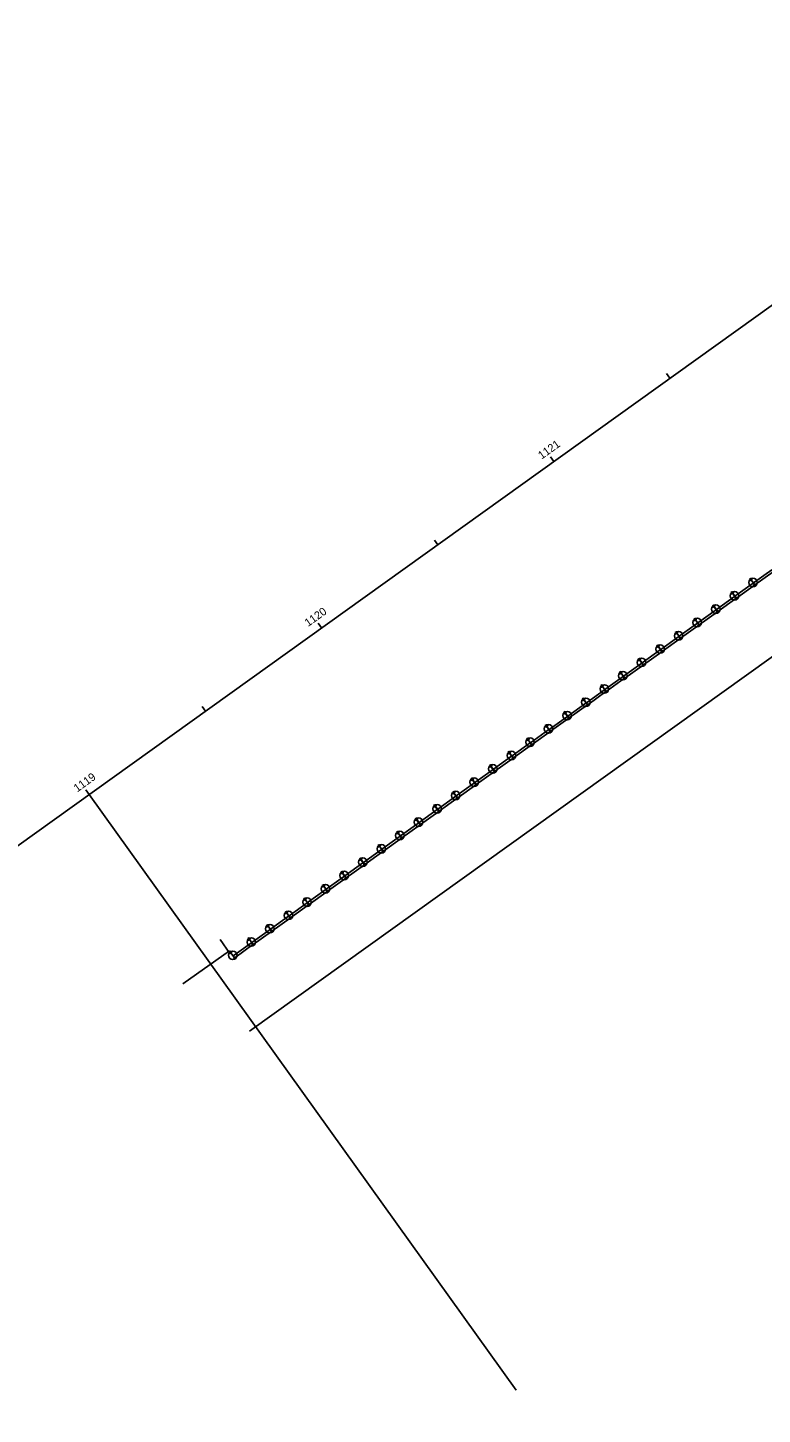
# Model space of a CAD drawing. Extents: x 2079879 to 2092887, y 778083 to 784051.
# Drawn here: x 2083884.9 to 2084142, y 780721.7 to 781206.9 of the extents above; entities that cross this region are included whole.
import ezdxf

# ---------------------------------------------------------------- set-up
doc = ezdxf.new("R2010")
doc.units = 0
for name, color, linetype in [('SC_Scratch1', 7, 'Continuous'), ('SH_Data', 7, 'Continuous'), ('SH_Text', 7, 'Continuous'), ('XS_X_Pavt', 7, 'Continuous')]:
    doc.layers.add(name, color=color, linetype=linetype)

msp = doc.modelspace()

# ---------------------------------------------------------------- linework, layer by layer
at = {"layer": 'SC_Scratch1'}
for p, q in [((2079923.52, 778084.44), (2085691.45, 782217.74)), ((2084109.66, 781084.22), (2084108.49, 781085.85)), ((2084069.02, 781055.1), (2084067.85, 781056.73)), ((2084028.37, 781025.98), (2084027.21, 781027.6)), ((2083987.73, 780996.85), (2083986.57, 780998.48)), ((2083947.09, 780967.73), (2083945.93, 780969.35)), ((2083906.45, 780938.6), (2083905.28, 780940.23))]:
    msp.add_line(p, q, dxfattribs=at)
at = {"layer": 'SH_Data'}
for p, q in [((2083962.54, 780855.77), (2084452.4, 781206.81)), ((2084138.06, 781013.69), (2084137.63, 781014.3)), ((2084131.56, 781009.03), (2084131.13, 781009.64)), ((2084125.06, 781004.37), (2084124.62, 781004.98)), ((2084118.55, 780999.71), (2084118.12, 781000.32)), ((2084112.05, 780995.05), (2084111.62, 780995.66)), ((2084105.55, 780990.39), (2084105.11, 780991)), ((2084099.04, 780985.73), (2084098.61, 780986.34)), ((2084092.54, 780981.07), (2084092.11, 780981.68)), ((2084086.04, 780976.41), (2084085.61, 780977.02)), ((2084079.54, 780971.75), (2084079.1, 780972.36)), ((2084073.03, 780967.09), (2084072.6, 780967.7)), ((2084066.53, 780962.43), (2084066.1, 780963.04)), ((2084060.03, 780957.77), (2084059.6, 780958.38)), ((2084053.53, 780953.11), (2084053.09, 780953.72)), ((2084040.52, 780943.79), (2084040.09, 780944.4)), ((2084047.02, 780948.45), (2084046.59, 780949.06)), ((2083906.45, 780938.6), (2084055.81, 780730.17)), ((2084027.51, 780934.47), (2084027.08, 780935.08)), ((2084021.01, 780929.81), (2084020.58, 780930.42)), ((2084014.51, 780925.15), (2084014.08, 780925.76)), ((2084008.01, 780920.49), (2084007.57, 780921.1)), ((2084001.5, 780915.83), (2084001.07, 780916.44)), ((2083995, 780911.17), (2083994.57, 780911.78)), ((2083988.5, 780906.51), (2083988.07, 780907.12)), ((2083982, 780901.85), (2083981.56, 780902.46)), ((2083975.49, 780897.19), (2083975.06, 780897.8)), ((2083968.99, 780892.53), (2083968.56, 780893.14)), ((2083955.65, 780882.97), (2083952.19, 780887.87)), ((2083962.49, 780887.87), (2083962.05, 780888.48)), ((2083955.55, 780883.82), (2083939.21, 780872.29)), ((2083955.98, 780883.21), (2083955.55, 780883.82))]:
    msp.add_line(p, q, dxfattribs=at)
at = {"layer": 'SH_Text'}
for centre in [(2084138.71, 781012.78), (2084132.21, 781008.12), (2084125.71, 781003.46), (2084119.21, 780998.8), (2084112.7, 780994.14), (2084106.2, 780989.48), (2084099.7, 780984.82), (2084093.19, 780980.16), (2084086.69, 780975.5), (2084080.19, 780970.84), (2084073.69, 780966.18), (2084067.18, 780961.52), (2084060.68, 780956.86), (2084054.18, 780952.2), (2084041.17, 780942.88), (2084047.68, 780947.54), (2084034.67, 780938.22), (2084028.17, 780933.56), (2084021.66, 780928.9), (2084015.16, 780924.24), (2084008.66, 780919.58), (2084002.16, 780914.92), (2083995.65, 780910.26), (2083989.15, 780905.6), (2083982.65, 780900.94), (2083976.15, 780896.28), (2083969.64, 780891.62), (2083963.14, 780886.96), (2083956.64, 780882.3)]:
    msp.add_circle(centre, 1.5, dxfattribs=at)
at = {"layer": 'XS_X_Pavt'}
for points in [[(2084138.93, 781012.62), (2084145.29, 781017.19), (2084145.78, 781016.51), (2084139.41, 781011.95)], [(2084132.42, 781007.96), (2084138.79, 781012.53), (2084139.28, 781011.85), (2084132.91, 781007.29)], [(2084137.72, 781013.44), (2084138.4, 781013.93), (2084138.42, 781013.9), (2084138.11, 781013.67), (2084139.37, 781011.92), (2084139.68, 781012.14), (2084139.71, 781012.11), (2084139.03, 781011.62), (2084139, 781011.66), (2084139.32, 781011.88), (2084138.06, 781013.64), (2084137.75, 781013.41)], [(2084125.92, 781003.3), (2084132.29, 781007.87), (2084132.77, 781007.19), (2084126.41, 781002.63)], [(2084131.22, 781008.78), (2084131.9, 781009.27), (2084131.92, 781009.24), (2084131.61, 781009.01), (2084132.87, 781007.26), (2084133.18, 781007.48), (2084133.2, 781007.45), (2084132.53, 781006.96), (2084132.5, 781007), (2084132.82, 781007.22), (2084131.56, 781008.98), (2084131.24, 781008.75)], [(2084119.42, 780998.64), (2084125.78, 781003.21), (2084126.27, 781002.53), (2084119.9, 780997.97)], [(2084124.72, 781004.12), (2084125.39, 781004.61), (2084125.42, 781004.58), (2084125.1, 781004.35), (2084126.36, 781002.6), (2084126.68, 781002.82), (2084126.7, 781002.79), (2084126.02, 781002.3), (2084126, 781002.34), (2084126.31, 781002.56), (2084125.05, 781004.32), (2084124.74, 781004.09)], [(2084112.91, 780993.98), (2084119.28, 780998.55), (2084119.77, 780997.87), (2084113.4, 780993.31)], [(2084118.21, 780999.46), (2084118.89, 780999.95), (2084118.92, 780999.92), (2084118.6, 780999.69), (2084119.86, 780997.94), (2084120.17, 780998.16), (2084120.2, 780998.13), (2084119.52, 780997.64), (2084119.5, 780997.68), (2084119.81, 780997.9), (2084118.55, 780999.66), (2084118.24, 780999.43)], [(2084106.41, 780989.32), (2084112.78, 780993.89), (2084113.26, 780993.21), (2084106.9, 780988.65)], [(2084111.71, 780994.8), (2084112.39, 780995.29), (2084112.41, 780995.26), (2084112.1, 780995.03), (2084113.36, 780993.28), (2084113.67, 780993.5), (2084113.69, 780993.47), (2084113.02, 780992.98), (2084112.99, 780993.02), (2084113.31, 780993.24), (2084112.05, 780995), (2084111.74, 780994.77)], [(2084099.91, 780984.66), (2084106.28, 780989.23), (2084106.76, 780988.55), (2084100.39, 780983.99)], [(2084105.21, 780990.14), (2084105.89, 780990.63), (2084105.91, 780990.6), (2084105.6, 780990.37), (2084106.85, 780988.62), (2084107.17, 780988.84), (2084107.19, 780988.81), (2084106.51, 780988.32), (2084106.49, 780988.36), (2084106.8, 780988.58), (2084105.55, 780990.34), (2084105.23, 780990.11)], [(2084093.41, 780980), (2084099.77, 780984.57), (2084100.26, 780983.89), (2084093.89, 780979.33)], [(2084098.71, 780985.48), (2084099.38, 780985.97), (2084099.41, 780985.94), (2084099.09, 780985.71), (2084100.35, 780983.96), (2084100.67, 780984.18), (2084100.69, 780984.15), (2084100.01, 780983.66), (2084099.99, 780983.7), (2084100.3, 780983.92), (2084099.04, 780985.68), (2084098.73, 780985.45)], [(2084086.9, 780975.34), (2084093.27, 780979.91), (2084093.76, 780979.23), (2084087.39, 780974.67)], [(2084092.2, 780980.83), (2084092.88, 780981.31), (2084092.9, 780981.28), (2084092.59, 780981.05), (2084093.85, 780979.3), (2084094.16, 780979.52), (2084094.19, 780979.49), (2084093.51, 780979), (2084093.49, 780979.04), (2084093.8, 780979.26), (2084092.54, 780981.02), (2084092.23, 780980.79)], [(2084080.4, 780970.68), (2084086.77, 780975.25), (2084087.25, 780974.57), (2084080.89, 780970.01)], [(2084085.7, 780976.17), (2084086.38, 780976.65), (2084086.4, 780976.62), (2084086.09, 780976.39), (2084087.35, 780974.64), (2084087.66, 780974.86), (2084087.68, 780974.83), (2084087.01, 780974.34), (2084086.98, 780974.38), (2084087.3, 780974.6), (2084086.04, 780976.36), (2084085.72, 780976.13)], [(2084073.9, 780966.03), (2084080.27, 780970.59), (2084080.75, 780969.91), (2084074.38, 780965.35)], [(2084079.2, 780971.51), (2084079.88, 780971.99), (2084079.9, 780971.96), (2084079.59, 780971.73), (2084080.84, 780969.98), (2084081.16, 780970.2), (2084081.18, 780970.17), (2084080.5, 780969.68), (2084080.48, 780969.72), (2084080.79, 780969.94), (2084079.53, 780971.7), (2084079.22, 780971.47)], [(2084067.4, 780961.37), (2084073.76, 780965.93), (2084074.25, 780965.25), (2084067.88, 780960.69)], [(2084072.69, 780966.85), (2084073.37, 780967.33), (2084073.4, 780967.3), (2084073.08, 780967.07), (2084074.34, 780965.32), (2084074.65, 780965.54), (2084074.68, 780965.51), (2084074, 780965.02), (2084073.98, 780965.06), (2084074.29, 780965.28), (2084073.03, 780967.04), (2084072.72, 780966.81)], [(2084060.89, 780956.71), (2084067.26, 780961.27), (2084067.75, 780960.59), (2084061.38, 780956.03)], [(2084066.19, 780962.19), (2084066.87, 780962.67), (2084066.89, 780962.64), (2084066.58, 780962.41), (2084067.84, 780960.66), (2084068.15, 780960.88), (2084068.18, 780960.85), (2084067.5, 780960.36), (2084067.47, 780960.4), (2084067.79, 780960.62), (2084066.53, 780962.38), (2084066.22, 780962.15)], [(2084054.39, 780952.05), (2084060.76, 780956.61), (2084061.24, 780955.93), (2084054.88, 780951.37)], [(2084059.69, 780957.53), (2084060.37, 780958.01), (2084060.39, 780957.98), (2084060.08, 780957.75), (2084061.34, 780956), (2084061.65, 780956.22), (2084061.67, 780956.19), (2084061, 780955.7), (2084060.97, 780955.74), (2084061.28, 780955.96), (2084060.03, 780957.72), (2084059.71, 780957.49)], [(2084047.89, 780947.39), (2084054.25, 780951.95), (2084054.74, 780951.27), (2084048.37, 780946.71)], [(2084053.19, 780952.87), (2084053.86, 780953.35), (2084053.89, 780953.32), (2084053.57, 780953.09), (2084054.83, 780951.34), (2084055.15, 780951.56), (2084055.17, 780951.53), (2084054.49, 780951.04), (2084054.47, 780951.08), (2084054.78, 780951.3), (2084053.52, 780953.06), (2084053.21, 780952.83)], [(2084041.38, 780942.73), (2084047.75, 780947.29), (2084048.24, 780946.61), (2084041.87, 780942.05)], [(2084046.68, 780948.21), (2084047.36, 780948.69), (2084047.39, 780948.66), (2084047.07, 780948.43), (2084048.33, 780946.68), (2084048.64, 780946.9), (2084048.67, 780946.87), (2084047.99, 780946.38), (2084047.97, 780946.42), (2084048.28, 780946.64), (2084047.02, 780948.4), (2084046.71, 780948.17)], [(2084034.88, 780938.07), (2084041.25, 780942.63), (2084041.73, 780941.95), (2084035.37, 780937.39)], [(2084040.18, 780943.55), (2084040.86, 780944.03), (2084040.88, 780944), (2084040.57, 780943.77), (2084041.83, 780942.02), (2084042.14, 780942.24), (2084042.16, 780942.21), (2084041.49, 780941.72), (2084041.46, 780941.76), (2084041.78, 780941.98), (2084040.52, 780943.74), (2084040.2, 780943.51)], [(2084027.18, 780934.23), (2084027.85, 780934.71), (2084027.88, 780934.68), (2084027.56, 780934.45), (2084028.82, 780932.7), (2084029.14, 780932.92), (2084029.16, 780932.89), (2084028.48, 780932.4), (2084028.46, 780932.44), (2084028.77, 780932.66), (2084027.51, 780934.42), (2084027.2, 780934.19)], [(2084028.38, 780933.41), (2084034.75, 780937.97), (2084035.23, 780937.29), (2084028.86, 780932.73)], [(2084033.68, 780938.89), (2084034.36, 780939.37), (2084034.38, 780939.34), (2084034.07, 780939.11), (2084035.32, 780937.36), (2084035.64, 780937.58), (2084035.66, 780937.55), (2084034.98, 780937.06), (2084034.96, 780937.1), (2084035.27, 780937.32), (2084034.02, 780939.08), (2084033.7, 780938.85)], [(2084020.67, 780929.57), (2084021.35, 780930.05), (2084021.37, 780930.02), (2084021.06, 780929.79), (2084022.32, 780928.04), (2084022.63, 780928.26), (2084022.66, 780928.23), (2084021.98, 780927.74), (2084021.95, 780927.78), (2084022.27, 780928), (2084021.01, 780929.76), (2084020.7, 780929.53)], [(2084021.88, 780928.75), (2084028.24, 780933.31), (2084028.73, 780932.63), (2084022.36, 780928.07)], [(2084014.17, 780924.91), (2084014.85, 780925.39), (2084014.87, 780925.36), (2084014.56, 780925.13), (2084015.82, 780923.38), (2084016.13, 780923.6), (2084016.15, 780923.57), (2084015.48, 780923.08), (2084015.45, 780923.12), (2084015.77, 780923.34), (2084014.51, 780925.1), (2084014.19, 780924.87)], [(2084015.37, 780924.09), (2084021.74, 780928.65), (2084022.23, 780927.97), (2084015.86, 780923.41)], [(2084007.67, 780920.25), (2084008.34, 780920.73), (2084008.37, 780920.7), (2084008.06, 780920.47), (2084009.31, 780918.72), (2084009.63, 780918.94), (2084009.65, 780918.91), (2084008.97, 780918.42), (2084008.95, 780918.46), (2084009.26, 780918.68), (2084008, 780920.44), (2084007.69, 780920.21)], [(2084008.87, 780919.43), (2084015.24, 780923.99), (2084015.72, 780923.31), (2084009.36, 780918.75)], [(2084001.16, 780915.59), (2084001.84, 780916.07), (2084001.87, 780916.04), (2084001.55, 780915.81), (2084002.81, 780914.06), (2084003.12, 780914.28), (2084003.15, 780914.25), (2084002.47, 780913.76), (2084002.45, 780913.8), (2084002.76, 780914.02), (2084001.5, 780915.78), (2084001.19, 780915.55)], [(2084002.37, 780914.77), (2084008.73, 780919.33), (2084009.22, 780918.65), (2084002.85, 780914.09)], [(2083994.66, 780910.93), (2083995.34, 780911.41), (2083995.36, 780911.38), (2083995.05, 780911.15), (2083996.31, 780909.4), (2083996.62, 780909.62), (2083996.65, 780909.59), (2083995.97, 780909.1), (2083995.94, 780909.14), (2083996.26, 780909.36), (2083995, 780911.12), (2083994.69, 780910.89)], [(2083995.86, 780910.11), (2084002.23, 780914.67), (2084002.72, 780913.99), (2083996.35, 780909.43)], [(2083988.16, 780906.27), (2083988.84, 780906.75), (2083988.86, 780906.72), (2083988.55, 780906.49), (2083989.81, 780904.74), (2083990.12, 780904.96), (2083990.14, 780904.93), (2083989.47, 780904.45), (2083989.44, 780904.48), (2083989.75, 780904.7), (2083988.5, 780906.46), (2083988.18, 780906.23)], [(2083989.36, 780905.45), (2083995.73, 780910.01), (2083996.21, 780909.33), (2083989.85, 780904.77)], [(2083976.36, 780896.13), (2083982.72, 780900.69), (2083983.21, 780900.01), (2083976.84, 780895.45)], [(2083981.66, 780901.61), (2083982.33, 780902.09), (2083982.36, 780902.06), (2083982.04, 780901.83), (2083983.3, 780900.08), (2083983.62, 780900.3), (2083983.64, 780900.27), (2083982.96, 780899.79), (2083982.94, 780899.82), (2083983.25, 780900.04), (2083981.99, 780901.8), (2083981.68, 780901.57)], [(2083982.86, 780900.79), (2083989.23, 780905.35), (2083989.71, 780904.67), (2083983.34, 780900.11)], [(2083969.85, 780891.47), (2083976.22, 780896.03), (2083976.71, 780895.35), (2083970.34, 780890.79)], [(2083975.15, 780896.95), (2083975.83, 780897.43), (2083975.85, 780897.4), (2083975.54, 780897.18), (2083976.8, 780895.42), (2083977.11, 780895.64), (2083977.14, 780895.61), (2083976.46, 780895.13), (2083976.44, 780895.16), (2083976.75, 780895.38), (2083975.49, 780897.14), (2083975.18, 780896.91)], [(2083963.35, 780886.81), (2083969.72, 780891.37), (2083970.2, 780890.69), (2083963.84, 780886.13)], [(2083968.65, 780892.29), (2083969.33, 780892.77), (2083969.35, 780892.74), (2083969.04, 780892.52), (2083970.3, 780890.76), (2083970.61, 780890.98), (2083970.63, 780890.95), (2083969.96, 780890.47), (2083969.93, 780890.5), (2083970.25, 780890.72), (2083968.99, 780892.48), (2083968.67, 780892.25)], [(2083956.85, 780882.15), (2083963.22, 780886.71), (2083963.7, 780886.03), (2083957.33, 780881.47)], [(2083962.15, 780887.63), (2083962.83, 780888.11), (2083962.85, 780888.08), (2083962.54, 780887.86), (2083963.79, 780886.1), (2083964.11, 780886.32), (2083964.13, 780886.29), (2083963.45, 780885.81), (2083963.43, 780885.84), (2083963.74, 780886.06), (2083962.49, 780887.82), (2083962.17, 780887.59)], [(2083955.65, 780882.97), (2083956.32, 780883.45), (2083956.35, 780883.42), (2083956.03, 780883.2), (2083957.29, 780881.44), (2083957.6, 780881.66), (2083957.63, 780881.63), (2083956.95, 780881.15), (2083956.93, 780881.18), (2083957.24, 780881.4), (2083955.98, 780883.16), (2083955.67, 780882.93)]]:
    msp.add_lwpolyline(points, close=True, dxfattribs=at)

# ---------------------------------------------------------------- texts
at = {"layer": 'SC_Scratch1'}
for s, p in [('1121', (2084064.75, 781055.74)), ('1120', (2083983.04, 780997.18)), ('1119', (2083902.23, 780939.27))]:
    msp.add_text(s, height=2.8, rotation=35.6254, dxfattribs=at).set_placement(p)

doc.saveas('drawing.dxf')
